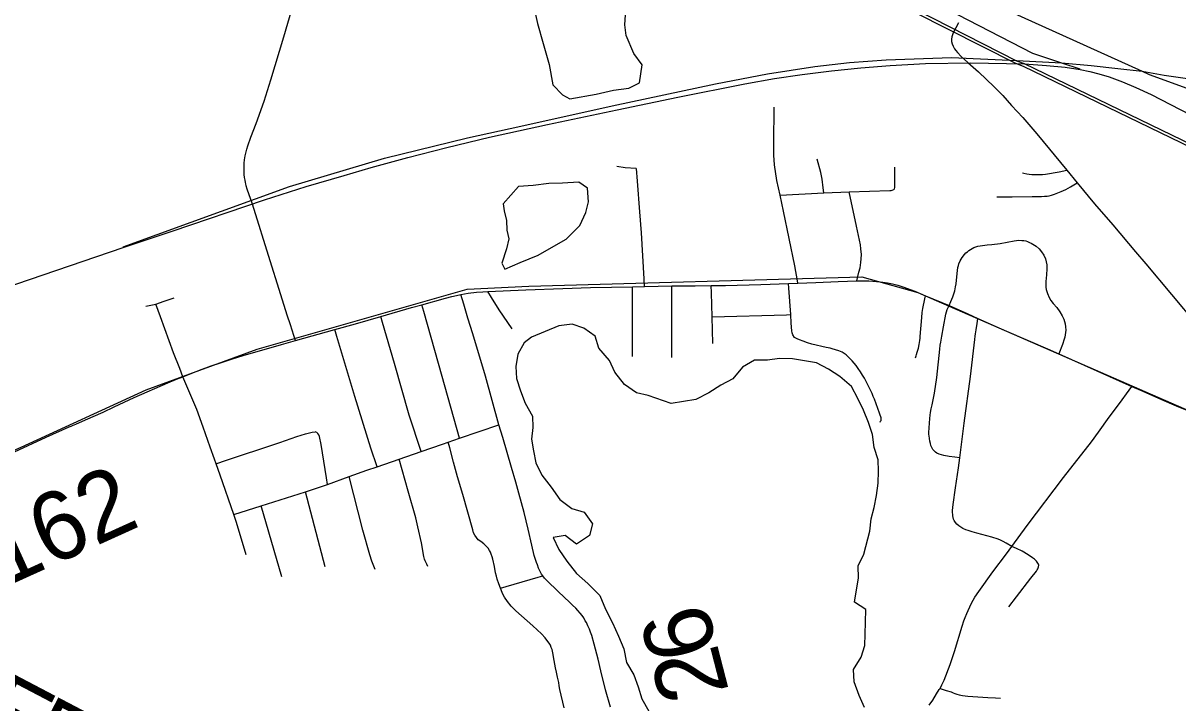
# Model space of a CAD drawing. Extents: x 0 to 34, y 0 to 22.
# Drawn here: x 3.593 to 4.548, y 14.848 to 15.41 of the extents above; entities that cross this region are included whole.
import ezdxf

# ---------------------------------------------------------------- set-up
doc = ezdxf.new("R2010")
doc.units = 0
for name, color, linetype in [('GM_X_County_Road', 7, 'Continuous'), ('GM_X_County_Road_Text', 7, 'Continuous'), ('GM_X_Major_Lake', 7, 'Continuous'), ('GM_X_Minor_Lake', 7, 'Continuous'), ('GM_X_Rail_Line', 7, 'Continuous'), ('GM_X_Township_Road', 7, 'Continuous'), ('GM_X_Township_Road_Text', 7, 'Continuous')]:
    doc.layers.add(name, color=color, linetype=linetype)

msp = doc.modelspace()

# ---------------------------------------------------------------- linework, layer by layer
at = {"layer": 'GM_X_County_Road'}
for p, q in [((4.45644, 15.28866), (4.46505, 15.27832)), ((4.2262, 15.19496), (4.23404, 15.19525)), ((4.09715, 15.19218), (4.10715, 15.19246)), ((4.10715, 15.19246), (4.12972, 15.19309)), ((4.33958, 15.18493), (4.35901, 15.17669)), ((3.81861, 15.14794), (3.85114, 15.15694))]:
    msp.add_line(p, q, dxfattribs=at)
for points in [[(3.77738, 15.27754), (3.77715, 15.27841), (3.77677, 15.28049), (3.77634, 15.28277), (3.77613, 15.28508), (3.77594, 15.28718), (3.77595, 15.28977), (3.77595, 15.29224), (3.7761, 15.29463), (3.77642, 15.29727), (3.77702, 15.30046), (3.77747, 15.30285), (3.77834, 15.30598), (3.77915, 15.30891), (3.78167, 15.31597), (3.78607, 15.32735), (3.79254, 15.34578), (3.79809, 15.36335), (3.80881, 15.39899), (3.82031, 15.43773)], [(4.36669, 15.41049), (4.36254, 15.40212), (4.36144, 15.39906), (4.36111, 15.39708), (4.36113, 15.39506), (4.36153, 15.39307), (4.36228, 15.3912), (4.36363, 15.38895), (4.36468, 15.38753), (4.366, 15.38594), (4.36902, 15.3827), (4.37459, 15.37763), (4.37675, 15.37573)], [(4.37675, 15.37573), (4.38325, 15.37001), (4.39633, 15.35772), (4.40345, 15.3505), (4.41078, 15.34227), (4.41989, 15.33218), (4.43155, 15.31865), (4.45644, 15.28866)], [(3.81861, 15.14794), (3.81719, 15.15215), (3.81429, 15.16076), (3.81175, 15.16891), (3.80507, 15.19006), (3.79753, 15.21376), (3.78284, 15.26056), (3.77861, 15.27294), (3.77785, 15.2758), (3.77738, 15.27754)], [(4.46505, 15.27832), (4.4794, 15.26078), (4.49442, 15.24349), (4.51331, 15.22121), (4.52185, 15.2114), (4.56414, 15.16047), (4.56612, 15.15801)], [(4.1624, 15.19329), (4.17409, 15.19341), (4.20326, 15.19416), (4.2262, 15.19496)], [(4.23404, 15.19525), (4.24889, 15.19579), (4.26729, 15.19654), (4.28278, 15.19711)], [(4.28278, 15.19711), (4.28678, 15.19725), (4.29264, 15.19709), (4.29889, 15.19667), (4.30412, 15.19606), (4.30811, 15.19551), (4.31228, 15.19476), (4.31658, 15.19362), (4.32066, 15.19238), (4.33064, 15.18878), (4.33958, 15.18493)], [(3.92292, 15.17745), (3.94269, 15.18293), (3.94792, 15.18426), (3.95179, 15.18516), (3.95524, 15.18594)], [(3.95524, 15.18594), (3.96145, 15.18705), (3.96807, 15.18778), (3.97354, 15.18822), (3.97765, 15.18838)], [(3.97765, 15.18838), (4.00914, 15.18967), (4.03947, 15.19085), (4.06235, 15.19159), (4.09715, 15.19218)], [(4.12972, 15.19309), (4.14893, 15.19316), (4.1624, 15.19329)], [(3.88897, 15.16768), (3.91445, 15.17504), (3.92292, 15.17745)], [(4.35901, 15.17669), (4.37458, 15.16984), (4.38274, 15.16621)], [(3.85114, 15.15694), (3.86801, 15.1616), (3.88897, 15.16768)], [(4.38274, 15.16621), (4.40467, 15.15645), (4.44229, 15.14009), (4.4498, 15.13673)], [(3.72547, 15.11796), (3.73215, 15.12063), (3.73902, 15.12324), (3.7489, 15.12689), (3.75561, 15.12924), (3.76643, 15.13272), (3.77534, 15.1355), (3.80698, 15.14456), (3.81861, 15.14794)], [(4.4498, 15.13673), (4.47066, 15.1274), (4.51024, 15.10999)], [(3.58624, 15.05593), (3.61225, 15.06785), (3.63136, 15.07645), (3.63301, 15.07717), (3.63407, 15.07759), (3.63686, 15.0788), (3.64479, 15.08227), (3.65954, 15.08863), (3.66846, 15.09294), (3.68522, 15.10077), (3.71304, 15.11287), (3.72005, 15.11579), (3.72547, 15.11796)], [(4.51024, 15.10999), (4.51731, 15.10689), (4.5348, 15.09918)], [(4.5348, 15.09918), (4.54694, 15.09394), (4.5584, 15.08922), (4.56665, 15.08598), (4.57013, 15.08461), (4.58898, 15.07801), (4.60561, 15.07297), (4.64261, 15.06281)]]:
    msp.add_lwpolyline(points, dxfattribs=at)
at = {"layer": 'GM_X_Major_Lake'}
msp.add_line((4.0364, 15.1599), (4.01376, 15.15062), dxfattribs=at)
for points in [[(4.28903, 14.84444), (4.28479, 14.85427), (4.28054, 14.86561), (4.28008, 14.87585), (4.28643, 14.88614), (4.28939, 14.89564), (4.28969, 14.90513), (4.28999, 14.91499), (4.29029, 14.92561), (4.28078, 14.93161), (4.28259, 14.94186), (4.28403, 14.95135), (4.28395, 14.96159), (4.28842, 14.97111), (4.29357, 14.99011), (4.29463, 15.00036), (4.2972, 15.00986), (4.29902, 15.01974), (4.30045, 15.02999), (4.30075, 15.03985), (4.30031, 15.04933), (4.2972, 15.05954), (4.2956, 15.07015), (4.2925, 15.07999), (4.28825, 15.09019), (4.28364, 15.10002), (4.27826, 15.10984), (4.26873, 15.1181), (4.25922, 15.1241), (4.24934, 15.12933), (4.23949, 15.13115), (4.22964, 15.13259), (4.21866, 15.13288), (4.20883, 15.13167), (4.19823, 15.13159), (4.18806, 15.12582), (4.18018, 15.11627), (4.17038, 15.11089), (4.16021, 15.10474), (4.14966, 15.09897), (4.12925, 15.09577), (4.11027, 15.10245), (4.10041, 15.10465), (4.09052, 15.1114), (4.08249, 15.12158), (4.07825, 15.13141), (4.06947, 15.14158), (4.06636, 15.15141), (4.05685, 15.15817), (4.04736, 15.16151), (4.0364, 15.1599)], [(4.01376, 15.15062), (4.00774, 15.14603), (4.00251, 15.1365), (4.0007, 15.12625), (4.00116, 15.11639), (4.00464, 15.10618), (4.00851, 15.09597), (4.01464, 15.0854), (4.01472, 15.07592), (4.01366, 15.06643), (4.01525, 15.05658), (4.01722, 15.04674), (4.02222, 15.03653), (4.02986, 15.02673), (4.03713, 15.01655), (4.04703, 15.00904), (4.05727, 15.00609), (4.06416, 14.99628), (4.06158, 14.98678), (4.05104, 14.97949), (4.04153, 14.98662), (4.0317, 14.98503), (4.03632, 14.97521), (4.04283, 14.9654), (4.05086, 14.95522), (4.06038, 14.94695)], [(4.06038, 14.94695), (4.0703, 14.93716), (4.07493, 14.92582), (4.08069, 14.91449), (4.0857, 14.90353), (4.08994, 14.89295), (4.0923, 14.88159), (4.09844, 14.87139), (4.10192, 14.86156), (4.10502, 14.85172), (4.11078, 14.84153), (4.11616, 14.83171), (4.11737, 14.8211), (4.11404, 14.81159), (4.10844, 14.80207), (4.09677, 14.79401), (4.08659, 14.78862), (4.07641, 14.78285), (4.06703, 14.7733), (4.06445, 14.7638), (4.06718, 14.75396), (4.07218, 14.74338), (4.08134, 14.73321), (4.08823, 14.72302)]]:
    msp.add_lwpolyline(points, dxfattribs=at)
at = {"layer": 'GM_X_Minor_Lake'}
msp.add_line((4.00295, 15.27531), (3.99019, 15.2608), dxfattribs=at)
for points in [[(4.01462, 15.42862), (4.01855, 15.41007), (4.02322, 15.39341), (4.02828, 15.37601), (4.03144, 15.35935), (4.03945, 15.35107), (4.04553, 15.3477), (4.06708, 15.35166), (4.08143, 15.35481), (4.09429, 15.35642), (4.10296, 15.36104), (4.10511, 15.37585), (4.09823, 15.38528), (4.09206, 15.40002), (4.09086, 15.40873), (4.09155, 15.41708)], [(3.99019, 15.2608), (3.991, 15.25512), (3.99295, 15.24717), (3.99339, 15.23921), (3.99496, 15.23202), (3.99313, 15.22366), (3.98906, 15.21187), (3.99175, 15.20696), (4.0042, 15.21237), (4.01929, 15.21855), (4.03398, 15.22701), (4.04227, 15.23163), (4.05354, 15.24309), (4.05875, 15.25375), (4.06096, 15.26249), (4.06011, 15.27386), (4.05288, 15.27874), (4.03926, 15.27787), (4.02791, 15.27778), (4.01505, 15.27616), (4.00295, 15.27531)]]:
    msp.add_lwpolyline(points, dxfattribs=at)
at = {"layer": 'GM_X_Rail_Line'}
for p, q in [((4.415, 15.37949), (4.45195, 15.37737)), ((4.45195, 15.37737), (4.46714, 15.3725))]:
    msp.add_line(p, q, dxfattribs=at)
for points in [[(3.61512, 15.77341), (3.67213, 15.76107), (3.71313, 15.74823), (3.75819, 15.72572), (3.81897, 15.69946), (3.97015, 15.62379), (4.10879, 15.55037), (4.42792, 15.38531), (4.45195, 15.37737)], [(4.22694, 15.50267), (4.51879, 15.37053)], [(4.97789, 15.10464), (4.42047, 15.37454), (4.41426, 15.37679), (4.33083, 15.41918)], [(4.97891, 15.10674), (4.42138, 15.37669), (4.4152, 15.37894), (4.3319, 15.42125)], [(3.48843, 15.16085), (3.67613, 15.22464), (3.71662, 15.23831), (3.79292, 15.26413), (3.82724, 15.27513), (3.8589, 15.28429), (3.88106, 15.29095), (3.91155, 15.29912), (3.9437, 15.30745), (3.97902, 15.31595), (4.02684, 15.32644), (4.0844, 15.33862), (4.13464, 15.34893), (4.19012, 15.3601), (4.21461, 15.36443), (4.23743, 15.36776), (4.26176, 15.37093), (4.28592, 15.37343), (4.31024, 15.37526), (4.33956, 15.37692), (4.37688, 15.37742), (4.42138, 15.37669), (4.43955, 15.3753), (4.45505, 15.37382), (4.46735, 15.37194), (4.47532, 15.37015), (4.48284, 15.36837), (4.49146, 15.36577), (4.50254, 15.36181), (4.51348, 15.35716), (4.5262, 15.35127), (4.7934, 15.21332)], [(3.67592, 15.2252), (3.81355, 15.27525), (3.8921, 15.29869), (3.96067, 15.31531), (4.00481, 15.32516), (4.08045, 15.34199), (4.16575, 15.36015), (4.20875, 15.36849), (4.24811, 15.37444), (4.2768, 15.37776), (4.30689, 15.37986), (4.36112, 15.38196), (4.415, 15.37949)], [(4.45195, 15.37737), (4.47655, 15.37517), (4.49865, 15.37289), (4.51879, 15.37053)], [(4.51879, 15.37053), (4.52457, 15.36791), (4.61015, 15.33666), (4.65085, 15.31597), (4.81883, 15.21702), (4.86055, 15.19283), (4.89705, 15.1712), (4.92206, 15.15318), (4.94777, 15.13465)], [(4.51879, 15.37053), (4.53696, 15.3672), (4.57362, 15.36206)], [(3.16164, 14.86917), (3.59155, 15.05975), (3.69491, 15.10708), (3.78672, 15.14078), (3.96052, 15.19041), (4.01136, 15.19279), (4.28694, 15.20058), (4.33328, 15.1875), (4.5683, 15.08516), (4.73764, 15.04002), (4.91046, 14.99642), (5.05215, 14.96737), (5.21112, 14.96194), (5.28222, 14.96063)]]:
    msp.add_lwpolyline(points, dxfattribs=at)
at = {"layer": 'GM_X_Township_Road'}
for p, q in [((4.21922, 15.26808), (4.25554, 15.26987)), ((4.25554, 15.26987), (4.27641, 15.27085)), ((4.16368, 15.14547), (4.1631, 15.16741)), ((3.95417, 15.0672), (3.98674, 15.07812)), ((3.94488, 15.06389), (3.95417, 15.0672)), ((3.90414, 15.04981), (3.92242, 15.05615)), ((3.88605, 15.04352), (3.90414, 15.04981)), ((3.84506, 15.02879), (3.86289, 15.03532)), ((3.7902, 15.01107), (3.82666, 15.0228)), ((3.82666, 15.0228), (3.84506, 15.02879)), ((3.843, 14.96072), (3.82666, 15.0228)), ((3.76744, 15.00409), (3.7902, 15.01107)), ((3.80714, 14.95259), (3.7902, 15.01107))]:
    msp.add_line(p, q, dxfattribs=at)
for points in [[(4.21922, 15.26808), (4.21658, 15.28024), (4.21466, 15.29317), (4.21401, 15.30098), (4.21409, 15.31093), (4.21443, 15.34078)], [(4.10029, 15.29017), (4.09109, 15.29074), (4.08436, 15.29171)], [(4.10715, 15.19246), (4.10677, 15.19898), (4.10456, 15.23685), (4.10332, 15.2542), (4.10131, 15.27969), (4.10047, 15.29016)], [(4.25554, 15.26987), (4.25503, 15.27399), (4.25413, 15.28131), (4.25306, 15.28674), (4.25005, 15.29793)], [(4.31387, 15.27332), (4.31411, 15.27448), (4.31413, 15.2751), (4.31405, 15.29126)], [(4.41985, 15.28658), (4.42098, 15.28612), (4.42321, 15.28561), (4.42528, 15.28536), (4.42758, 15.28512), (4.43011, 15.28499), (4.43194, 15.285), (4.4338, 15.28502), (4.4363, 15.28523), (4.4387, 15.28551), (4.45011, 15.28735), (4.45644, 15.28866)], [(4.27641, 15.27085), (4.31017, 15.2719), (4.31119, 15.27196), (4.31189, 15.27208), (4.31341, 15.27267), (4.31387, 15.27329)], [(4.39845, 15.26678), (4.41122, 15.26677), (4.42781, 15.26683), (4.43556, 15.267), (4.43787, 15.26713), (4.44017, 15.26731), (4.44186, 15.2676), (4.4438, 15.26809), (4.44611, 15.26893), (4.4516, 15.27095), (4.45558, 15.27276), (4.45936, 15.27498), (4.46505, 15.27832)], [(4.23404, 15.19525), (4.23369, 15.1972), (4.23145, 15.20972), (4.22206, 15.25492), (4.21922, 15.26808)], [(4.28278, 15.19711), (4.28451, 15.20439), (4.28537, 15.208), (4.28601, 15.21229), (4.28642, 15.2155), (4.2865, 15.21903), (4.28618, 15.22364), (4.28569, 15.22685), (4.28253, 15.24242), (4.27641, 15.27085)], [(4.35901, 15.17669), (4.36053, 15.18005), (4.36205, 15.18389), (4.36366, 15.18891), (4.36441, 15.19226), (4.36481, 15.19461), (4.36563, 15.20321), (4.36632, 15.20821), (4.3667, 15.20987), (4.36715, 15.21134), (4.36818, 15.21373), (4.36985, 15.2165), (4.37184, 15.21903), (4.37301, 15.22023), (4.37415, 15.22129), (4.3755, 15.22236), (4.37677, 15.22321), (4.3781, 15.22404), (4.37962, 15.22472), (4.38111, 15.22531), (4.38292, 15.22583), (4.38464, 15.22618), (4.38663, 15.22649), (4.39049, 15.22689), (4.3945, 15.22723), (4.40121, 15.22815), (4.41281, 15.23032), (4.41483, 15.23061), (4.41673, 15.23075), (4.41924, 15.23069), (4.42085, 15.2305), (4.42252, 15.23015), (4.42402, 15.22963), (4.4255, 15.22903), (4.42697, 15.22835), (4.42838, 15.22758), (4.42975, 15.22667), (4.43105, 15.22577), (4.43347, 15.22362), (4.43556, 15.22116), (4.43731, 15.21845), (4.43869, 15.21551), (4.43943, 15.21302), (4.43983, 15.21034), (4.43995, 15.20724), (4.43958, 15.2022), (4.43897, 15.19671), (4.439, 15.19381), (4.43916, 15.19197), (4.43943, 15.19016), (4.43985, 15.18839), (4.44038, 15.18669), (4.44179, 15.18338), (4.4433, 15.18084), (4.44518, 15.17854), (4.4481, 15.17524), (4.4507, 15.17163), (4.45261, 15.16833), (4.4539, 15.1654), (4.455, 15.1617), (4.45543, 15.15918), (4.45559, 15.15647), (4.4554, 15.15455), (4.45512, 15.15269), (4.4547, 15.15067), (4.45423, 15.14894), (4.45279, 15.1446), (4.4498, 15.13673)], [(4.30193, 15.08042), (4.30241, 15.08113), (4.30274, 15.08184), (4.30294, 15.08259), (4.30277, 15.08396), (4.30256, 15.08477), (4.30207, 15.08617), (4.30154, 15.0877), (4.29736, 15.09938), (4.29637, 15.1017), (4.29541, 15.10396), (4.28896, 15.11672), (4.28739, 15.11936), (4.28576, 15.12209), (4.28397, 15.12467), (4.28218, 15.12724), (4.28064, 15.12909), (4.27894, 15.13112), (4.27677, 15.1333), (4.27537, 15.13471), (4.27389, 15.13591), (4.27238, 15.13715), (4.2707, 15.13811), (4.26921, 15.13875), (4.26777, 15.13938), (4.26521, 15.14017), (4.26234, 15.14106), (4.26065, 15.14146), (4.25751, 15.14221), (4.24558, 15.14499), (4.24202, 15.14593), (4.23826, 15.14733), (4.23542, 15.14843), (4.23345, 15.14916), (4.23133, 15.15046), (4.22968, 15.15256), (4.2292, 15.15413), (4.22902, 15.15586), (4.22853, 15.16208), (4.22805, 15.16925), (4.22647, 15.19114), (4.2262, 15.19496)], [(4.079, 14.84464), (4.07496, 14.85894), (4.07108, 14.87464), (4.06869, 14.88429), (4.06555, 14.89692), (4.06347, 14.90402), (4.06249, 14.90668), (4.06156, 14.9092), (4.06025, 14.91211), (4.05904, 14.91478), (4.05821, 14.91621), (4.0569, 14.91846), (4.05549, 14.9204), (4.05404, 14.9224), (4.05201, 14.9247), (4.05039, 14.92652), (4.04767, 14.9291), (4.04502, 14.93161), (4.03592, 14.94011), (4.02612, 14.94966), (4.02451, 14.95133), (4.02297, 14.95341), (4.02203, 14.95471), (4.02103, 14.9564), (4.02023, 14.95799), (4.01952, 14.95973), (4.01856, 14.96232), (4.01778, 14.9644), (4.01588, 14.97014), (4.01385, 14.97861), (4.01085, 14.99192), (4.00759, 15.00575), (4.00334, 15.02154), (4.00066, 15.03073), (3.9971, 15.04291), (3.98986, 15.06776), (3.98674, 15.07812), (3.97569, 15.1184), (3.96514, 15.15339), (3.96115, 15.16628), (3.95761, 15.17805), (3.95524, 15.18594)], [(3.99762, 15.15755), (3.98698, 15.17322), (3.9807, 15.18334), (3.97765, 15.18838)], [(4.09734, 15.13477), (4.09717, 15.18683), (4.09715, 15.19218)], [(4.12983, 15.13377), (4.12973, 15.18788), (4.12972, 15.19309)], [(4.1631, 15.16741), (4.16256, 15.18735), (4.1624, 15.19329)], [(3.69463, 15.17637), (3.7031, 15.17783), (3.71003, 15.18035), (3.7183, 15.1832)], [(3.72547, 15.11796), (3.72281, 15.12471), (3.71771, 15.13764), (3.70684, 15.16738), (3.7031, 15.17783)], [(3.95417, 15.0672), (3.93971, 15.11825), (3.92453, 15.17181), (3.92292, 15.17745)], [(4.3313, 15.13368), (4.33174, 15.13508), (4.33213, 15.13632), (4.33274, 15.1383), (4.3333, 15.13998), (4.33374, 15.14167), (4.33425, 15.14448), (4.33451, 15.14629), (4.33474, 15.14798), (4.33499, 15.14971), (4.33521, 15.15128), (4.33642, 15.16685), (4.33681, 15.17099), (4.3374, 15.17428), (4.33907, 15.18246), (4.33958, 15.18493)], [(4.36779, 15.05085), (4.36392, 15.05134), (4.35905, 15.05196), (4.35481, 15.0528), (4.3528, 15.05329), (4.35072, 15.05396), (4.34901, 15.05483), (4.34788, 15.05546), (4.34688, 15.0563), (4.34554, 15.05788), (4.34479, 15.05938), (4.34404, 15.06108), (4.34361, 15.0628), (4.34313, 15.0647), (4.3428, 15.06673), (4.34244, 15.06894), (4.34239, 15.07015), (4.34233, 15.07187), (4.34305, 15.08341), (4.34331, 15.08616), (4.34372, 15.08841), (4.34433, 15.09137), (4.34501, 15.09466), (4.34692, 15.10437), (4.34904, 15.11726), (4.35143, 15.14078), (4.35176, 15.14389), (4.35209, 15.14639), (4.35238, 15.14818), (4.35301, 15.15138), (4.35452, 15.15915), (4.35644, 15.16958), (4.35693, 15.17168), (4.35755, 15.17342), (4.35901, 15.17669)], [(3.92242, 15.05615), (3.91264, 15.08615), (3.90036, 15.12885), (3.89038, 15.16284), (3.88897, 15.16768)], [(4.1631, 15.16741), (4.22461, 15.16916), (4.22805, 15.16925)], [(4.41099, 14.97764), (4.40637, 14.98025), (4.40383, 14.98168), (4.40162, 14.98277), (4.39966, 14.98361), (4.39789, 14.98419), (4.39615, 14.98478), (4.39442, 14.98529), (4.38192, 14.98866), (4.37822, 14.9897), (4.37474, 14.99075), (4.37288, 14.99137), (4.37054, 14.99246), (4.36863, 14.99355), (4.36712, 14.99463), (4.36554, 14.99597), (4.36439, 14.99731), (4.36328, 14.99905), (4.36279, 15.00014), (4.36246, 15.00164), (4.36221, 15.00281), (4.36204, 15.00414), (4.36187, 15.00565), (4.3619, 15.00737), (4.36233, 15.01243), (4.36441, 15.02594), (4.36674, 15.04255), (4.36779, 15.05085), (4.3714, 15.0794), (4.37664, 15.11801), (4.38038, 15.1488), (4.38071, 15.15147), (4.38096, 15.15347), (4.38138, 15.15673), (4.38214, 15.16198), (4.38274, 15.16621)], [(3.88605, 15.04352), (3.88091, 15.05887), (3.8677, 15.10148), (3.85275, 15.15132), (3.85114, 15.15694)], [(3.75286, 15.04583), (3.75147, 15.04984), (3.74807, 15.05982), (3.74224, 15.07624), (3.73679, 15.09083), (3.72547, 15.11796)], [(4.34269, 14.84636), (4.34547, 14.85039), (4.34876, 14.8557), (4.35094, 14.85921), (4.35153, 14.86026), (4.35314, 14.86314), (4.35487, 14.86707), (4.35987, 14.8801), (4.36348, 14.89079), (4.3699, 14.91183), (4.37137, 14.91598), (4.37237, 14.91884), (4.37379, 14.92223), (4.37477, 14.92459), (4.37625, 14.9278), (4.37764, 14.93083), (4.37902, 14.93332), (4.38038, 14.93577), (4.38351, 14.94049), (4.39511, 14.95665), (4.40639, 14.97153), (4.41099, 14.97764), (4.42372, 14.99484), (4.45377, 15.03452), (4.47695, 15.06414), (4.48273, 15.0721), (4.4915, 15.08458), (4.49995, 15.09589), (4.50796, 15.10687), (4.51024, 15.10999)], [(3.75286, 15.04583), (3.75816, 15.04773), (3.80567, 15.06363), (3.81975, 15.06844), (3.82684, 15.07067), (3.83217, 15.07216), (3.83492, 15.07248)], [(3.84506, 15.02879), (3.84413, 15.03442), (3.83961, 15.06178), (3.83828, 15.06842), (3.83787, 15.06977), (3.83708, 15.07095), (3.83603, 15.07195), (3.83492, 15.07248)], [(3.92242, 15.05615), (3.94012, 15.0623), (3.94488, 15.06389)], [(3.98794, 14.94308), (3.98665, 14.94682), (3.98542, 14.95047), (3.98476, 14.95305), (3.98404, 14.9558), (3.98309, 14.96111), (3.98173, 14.96715), (3.9811, 14.96909), (3.98038, 14.97127), (3.97984, 14.97275), (3.97894, 14.97434), (3.97774, 14.97613), (3.97674, 14.97722), (3.97565, 14.97842), (3.97417, 14.97971), (3.97178, 14.98161), (3.96969, 14.9832), (3.96814, 14.9849), (3.96681, 14.98698), (3.96581, 14.98898), (3.96506, 14.99122), (3.95681, 15.02044), (3.9525, 15.03526), (3.94922, 15.0473), (3.9461, 15.05923), (3.94488, 15.06389)], [(3.76744, 15.00409), (3.75611, 15.03641), (3.75286, 15.04583)], [(3.86289, 15.03532), (3.87752, 15.04056), (3.88605, 15.04352)], [(3.92793, 14.961), (3.92703, 14.96303), (3.92587, 14.96561), (3.92526, 14.96722), (3.92472, 14.96936), (3.92269, 14.98049), (3.9198, 14.99385), (3.91792, 15.0013), (3.91173, 15.02331), (3.90414, 15.04981)], [(3.88454, 14.95859), (3.8832, 14.96136), (3.88159, 14.96533), (3.87997, 14.97065), (3.87411, 14.99103), (3.86289, 15.03532)], [(3.77781, 14.97077), (3.76976, 14.99748), (3.76744, 15.00409)], [(4.40849, 14.92779), (4.41471, 14.93594), (4.42659, 14.95131), (4.43122, 14.95717), (4.43195, 14.95819), (4.43253, 14.95923), (4.43304, 14.96079), (4.43313, 14.96211), (4.43295, 14.96289), (4.43249, 14.96389), (4.43189, 14.96468), (4.43136, 14.96534), (4.4307, 14.96613), (4.42963, 14.9671), (4.42806, 14.96832), (4.42453, 14.97065), (4.41941, 14.97373), (4.41486, 14.976), (4.41099, 14.97764)], [(3.98794, 14.94308), (3.99261, 14.94445), (4.0191, 14.95227), (4.02297, 14.95341)], [(4.04081, 14.84407), (4.03712, 14.85946), (4.03659, 14.86234), (4.03616, 14.86518), (4.03512, 14.86949), (4.03446, 14.87357), (4.03363, 14.87738), (4.03254, 14.88336), (4.03145, 14.88972), (4.03072, 14.8925), (4.03006, 14.89411), (4.0293, 14.89593), (4.0283, 14.89755), (4.02733, 14.89912), (4.02502, 14.90208), (4.02205, 14.90526), (4.01466, 14.91191), (4.00078, 14.92433), (3.99689, 14.92833), (3.99375, 14.93216), (3.99142, 14.93567), (3.99027, 14.93771), (3.98941, 14.9395), (3.98794, 14.94308)], [(4.35153, 14.86026), (4.35671, 14.85864), (4.36082, 14.85736), (4.36238, 14.85671), (4.36369, 14.85609), (4.36537, 14.85546), (4.36743, 14.85498), (4.37018, 14.85451), (4.37223, 14.85421), (4.37444, 14.8539), (4.39117, 14.85276), (4.39732, 14.85237), (4.40162, 14.85214)]]:
    msp.add_lwpolyline(points, dxfattribs=at)

# ---------------------------------------------------------------- texts
at = {"layer": 'GM_X_County_Road_Text'}
msp.add_text('C-162', height=0.056818, rotation=24.35303, dxfattribs=at).set_placement((3.50314, 14.90982))
at = {"layer": 'GM_X_Township_Road_Text'}
for s, rotation, p in [('6', 104.77015, (4.16838, 14.89206)), ('2', 104.48251, (4.17721, 14.85787)), ('E', 332.31001, (3.55285, 14.82511)), ('R', 332.32255, (3.5905, 14.80536))]:
    msp.add_text(s, height=0.05682, rotation=rotation, dxfattribs=at).set_placement(p)

doc.saveas('drawing.dxf')
